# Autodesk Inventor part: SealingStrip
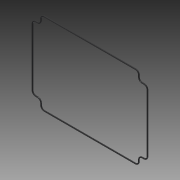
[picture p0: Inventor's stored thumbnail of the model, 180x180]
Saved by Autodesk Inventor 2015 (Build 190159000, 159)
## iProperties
Created: 2014-07
Part Number: SealingStrip
Material: Rubber
Document SubType Name: Modeling
Designer: Gavin
Density: 0.93 g/cm^3
Appearance: Rubber - Black - Version 1.1
Author: Gavin
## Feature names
1. Sweep1
## Parameters: d1 = 2.5 mm, d2 = 0, d3 = 0
